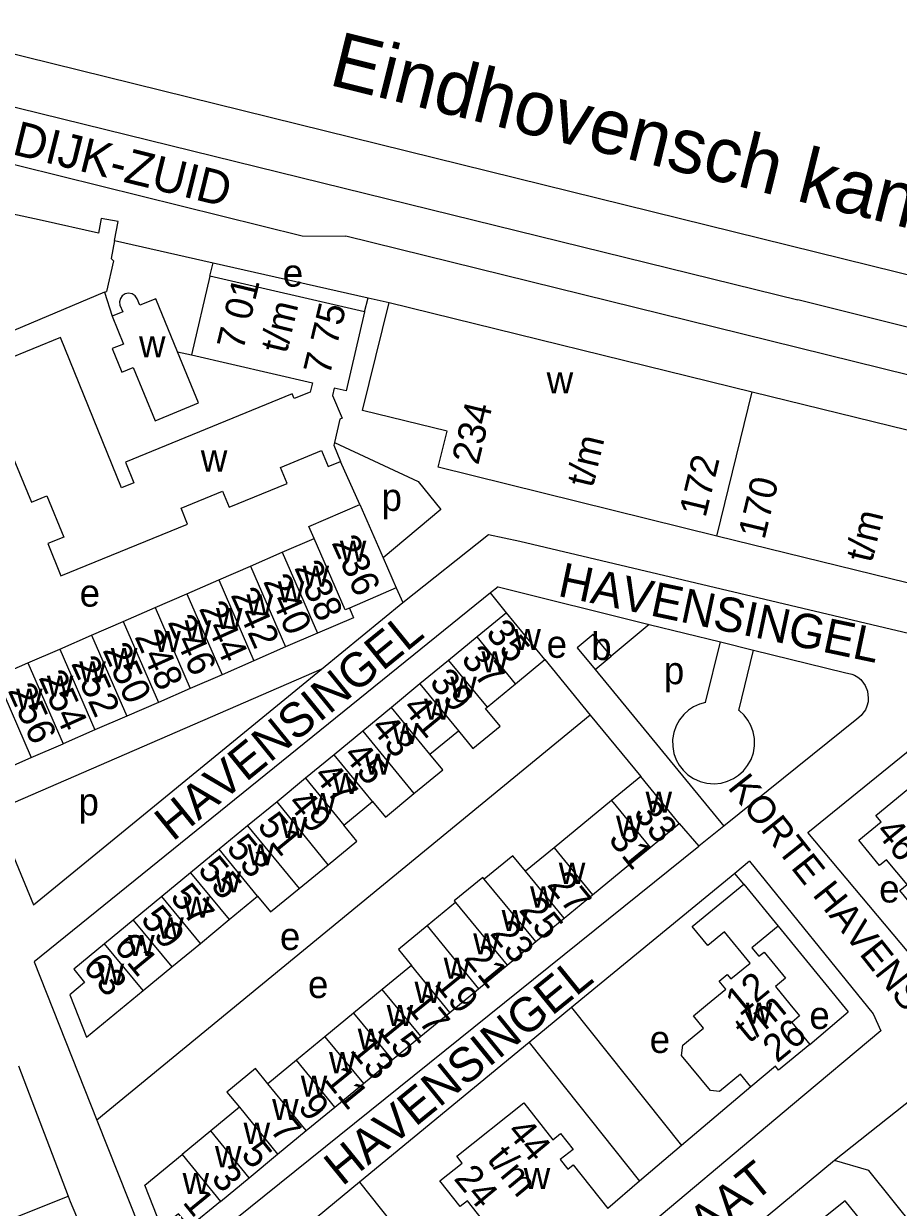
# Model space of a CAD drawing. Extents: x 161141 to 163125, y 381621 to 383200.
# Drawn here: x 161949.3 to 162076.7, y 382970.4 to 383142.8 of the extents above; entities that cross this region are included whole.
import ezdxf

# ---------------------------------------------------------------- set-up
doc = ezdxf.new("R2010")
doc.units = 0
for name, color, linetype in [('BLT_Basislijn', 7, 'Continuous'), ('BLT_Bebouwing', 7, 'Continuous'), ('BLT_Centroide', 7, 'Continuous'), ('BLT_Huisnummer', 7, 'Continuous'), ('BLT_Huisnummer_ tussenligend', 7, 'Continuous'), ('BLT_Huisnummer_reeks', 7, 'Continuous'), ('BLT_Onderverdeling_panden', 7, 'Continuous'), ('BLT_Straatnaam', 7, 'Continuous'), ('BLT_Vlakafsluiter', 7, 'Continuous'), ('BLT_Waternaam_spoorwegen', 7, 'Continuous')]:
    doc.layers.add(name, color=color, linetype=linetype)

msp = doc.modelspace()

# ---------------------------------------------------------------- linework, layer by layer
at = {"layer": 'BLT_Basislijn'}
for p, q in [((161930.08, 383142.85), (162162.91, 383085.35)), ((161940.74, 383132.45), (162062.11, 383102.59)), ((162049.96, 383098.62), (161996.22, 383111.86)), ((161962.54, 383111.24), (161976.92, 383108)), ((161976.41, 383106.07), (161976.92, 383108)), ((161976.92, 383108), (161999.47, 383102.91)), ((161961.09, 383103.72), (161962.2, 383100.21)), ((161998.98, 383100.85), (161999.47, 383102.91)), ((161999.47, 383102.91), (162002.55, 383102.22)), ((161971.72, 383095.01), (161973.74, 383094.58)), ((161998.26, 383072.8), (161995.46, 383079.07)), ((162003.56, 383060.66), (162004.54, 383058.52)), ((161992.67, 383048.8), (162004.54, 383058.52)), ((162019.63, 383057.02), (162017.33, 383059.89)), ((162048.63, 383043.94), (162050.81, 383052.77)), ((162053.5, 383042.79), (162055.66, 383051.57)), ((162025.22, 383050.18), (162031.86, 383042.1)), ((161992.67, 383048.8), (161945.03, 383028.11)), ((162031.86, 383042.1), (161959.96, 382983.09)), ((162031.86, 383042.1), (162039.2, 383033.15)), ((162044.82, 383026.32), (162047.68, 383022.98)), ((162051.3, 383025.9), (162047.68, 383022.98)), ((162055.07, 383020.8), (162052.92, 383019.04)), ((162052.92, 383019.04), (162029.14, 382999.47)), ((162054.21, 383017.47), (162052.92, 383019.04)), ((162059.25, 383011.35), (162069.42, 382998.87)), ((162029.14, 382999.47), (162022.96, 382994.38)), ((162063.84, 382994.12), (162069.42, 382998.87)), ((162022.96, 382994.38), (161998.24, 382974.04)), ((162022.96, 382994.38), (162039.04, 382974.17)), ((161948.53, 382991.01), (161955.76, 382972.02)), ((162055.23, 382987.95), (162045.14, 382979.36)), ((162045.14, 382979.36), (162039.04, 382974.17)), ((161998.24, 382974.04), (161992.06, 382968.95)), ((162039.04, 382974.17), (162034.4, 382970.22)), ((161932.99, 382962.83), (161955.76, 382972.02))]:
    msp.add_line(p, q, dxfattribs=at)
for points in [[(161919.31, 383129.41), (161989.89, 383111.92), (161996.22, 383111.86)], [(162151.84, 383081.16), (162138.64, 383083.46), (162062.11, 383102.59)], [(162150.16, 383071.14), (162119.18, 383081.51), (162049.96, 383098.62)], [(161994.6, 383081.83), (162006.79, 383076.12), (162010.09, 383072.07), (162001.66, 383065.01)], [(162004.54, 383058.52), (162017.04, 383068.43), (162021.59, 383067.42)], [(162021.59, 383067.42), (162082.93, 383052.93)], [(162018.42, 383060.77), (162017.33, 383059.89)], [(162018.42, 383060.77), (162040.46, 383055.32)], [(162017.33, 383059.89), (161950.81, 383006.16), (161959.96, 382983.09)], [(162040.46, 383055.32), (162034.89, 383050.66)], [(162040.46, 383055.32), (162050.81, 383052.77)], [(162050.81, 383052.77), (162055.66, 383051.57)], [(162055.66, 383051.57), (162068.91, 383048.3), (162069.96, 383048.05), (162070.38, 383047.93), (162070.86, 383047.62), (162071.3, 383047.29), (162071.68, 383046.75), (162071.91, 383046.42), (162072.25, 383045.6)], [(161945.03, 383028.11), (161950.71, 383014.47), (161992.67, 383048.8)], [(162032.58, 383048.72), (162051.3, 383025.9)], [(162072.25, 383045.6), (162072.36, 383044.56), (162072.34, 383044.01), (162072.15, 383043.4), (162071.94, 383042.86), (162071.58, 383042.37), (162071.35, 383042.02), (162070.71, 383041.5), (162051.3, 383025.9)], [(162048.63, 383043.94), (162047.78, 383043.71), (162046.92, 383043.32), (162046.17, 383042.82), (162045.47, 383042.19), (162044.86, 383041.42), (162044.36, 383040.53), (162044.02, 383039.55), (162043.85, 383038.52), (162043.87, 383037.5), (162044.05, 383036.51), (162044.38, 383035.6), (162044.82, 383034.8)], [(162044.82, 383034.8), (162045.38, 383034.07), (162046.08, 383033.41), (162046.91, 383032.85), (162047.85, 383032.43), (162048.86, 383032.18), (162049.89, 383032.1), (162050.91, 383032.2), (162051.86, 383032.46), (162052.72, 383032.85), (162053.47, 383033.34), (162054.17, 383033.97), (162054.78, 383034.74), (162055.28, 383035.63), (162055.62, 383036.61), (162055.79, 383037.64), (162055.77, 383038.67), (162055.59, 383039.65), (162055.26, 383040.56), (162054.82, 383041.36)], [(162054.82, 383041.36), (162054.26, 383042.09), (162053.56, 383042.75), (162053.5, 383042.79)], [(162079.29, 383006.24), (162063.54, 383024.97), (162082.54, 383040.38)], [(161959.96, 382983.09), (161969.17, 382959.86), (162047.68, 383022.98)], [(162055.07, 383020.8), (162073.06, 382998.55), (162074.21, 382996.11), (162061.33, 382985.3), (162036.1, 382964.14), (162021.9, 382952.54)], [(162029.14, 382999.47), (162045.14, 382979.36)], [(162067.43, 382977.19), (162051.8, 382964.24)], [(162134.11, 382898.87), (162072.44, 382975.73), (162067.43, 382977.19)], [(161998.24, 382974.04), (162010.67, 382958.41), (162004.41, 382953.43)], [(161955.76, 382972.02), (161956.08, 382971.21), (161959.35, 382963.42), (161964.45, 382950.31), (161972.02, 382931.93), (161975.96, 382922.03)]]:
    msp.add_lwpolyline(points, dxfattribs=at)
at = {"layer": 'BLT_Bebouwing'}
for p, q in [((161951.99, 383114.15), (161922.23, 383120.74)), ((161961.09, 383103.72), (161961.35, 383103.82)), ((162002.55, 383102.22), (162055.46, 383089.21)), ((162055.46, 383089.21), (162103.01, 383077.48)), ((161986.98, 383065.82), (161991.6, 383067.83)), ((162090.75, 383058.21), (162050.29, 383068.19)), ((161982.34, 383063.8), (161986.98, 383065.82)), ((161977.71, 383061.79), (161982.34, 383063.8)), ((161973.08, 383059.77), (161977.71, 383061.79)), ((161968.45, 383057.76), (161973.08, 383059.77)), ((161963.81, 383055.75), (161968.45, 383057.76)), ((162019.63, 383057.02), (162015.37, 383053.51)), ((162025.22, 383050.18), (162019.63, 383057.02)), ((161959.18, 383053.73), (161963.81, 383055.75)), ((161954.55, 383051.72), (161959.18, 383053.73)), ((161992.1, 383054.03), (161987.47, 383052.02)), ((162015.37, 383053.51), (162011.2, 383050.07)), ((161949.92, 383049.7), (161954.55, 383051.72)), ((161987.47, 383052.02), (161982.84, 383050)), ((162029.96, 383051.9), (162032.58, 383048.72)), ((161982.84, 383050), (161978.2, 383047.98)), ((162011.2, 383050.07), (162007.04, 383046.64)), ((162020.95, 383046.67), (162025.22, 383050.18)), ((161945.28, 383047.69), (161949.92, 383049.7)), ((161978.2, 383047.98), (161973.57, 383045.97)), ((162007.04, 383046.64), (162002.87, 383043.2)), ((162016.81, 383043.25), (162020.95, 383046.67)), ((161973.57, 383045.97), (161968.94, 383043.95)), ((161968.94, 383043.95), (161964.31, 383041.94)), ((162002.87, 383043.2), (161998.71, 383039.77)), ((161964.31, 383041.94), (161959.67, 383039.93)), ((161959.67, 383039.93), (161955.04, 383037.91)), ((161998.71, 383039.77), (161994.54, 383036.33)), ((162008.48, 383036.39), (162012.64, 383039.82)), ((161950.41, 383035.9), (161955.04, 383037.91)), ((161994.54, 383036.33), (161990.37, 383032.91)), ((161990.37, 383032.91), (161986.21, 383029.48)), ((162039.2, 383033.15), (162034.96, 383029.65)), ((162044.82, 383026.32), (162039.2, 383033.15)), ((161986.21, 383029.48), (161981.93, 383025.96)), ((161995.97, 383026.07), (162000.14, 383029.52)), ((162034.96, 383029.65), (162030.75, 383026.19)), ((161981.93, 383025.96), (161977.78, 383022.54)), ((162030.75, 383026.19), (162026.6, 383022.76)), ((162040.59, 383022.82), (162044.82, 383026.32)), ((161977.78, 383022.54), (161973.6, 383019.1)), ((162026.6, 383022.76), (162022.44, 383019.34)), ((162036.38, 383019.36), (162040.59, 383022.82)), ((161973.6, 383019.1), (161969.43, 383015.66)), ((161989.43, 383016.82), (161993.65, 383020.27)), ((162032.16, 383015.89), (162036.38, 383019.36)), ((162046.72, 383011.3), (162054.21, 383017.47)), ((161969.43, 383015.66), (161965.25, 383012.22)), ((161979.24, 383012.29), (161983.38, 383015.7)), ((162028.07, 383012.53), (162032.16, 383015.89)), ((162012.21, 383014.8), (162008.08, 383011.39)), ((161965.25, 383012.22), (161961.07, 383008.78)), ((161975.05, 383008.83), (161979.24, 383012.29)), ((162023.91, 383009.09), (162028.07, 383012.53)), ((161970.88, 383005.4), (161975.05, 383008.83)), ((162019.74, 383005.66), (162023.91, 383009.09)), ((161966.73, 383001.98), (161970.88, 383005.4)), ((162005.81, 383005.63), (162001.55, 383002.12)), ((162015.56, 383002.22), (162019.74, 383005.66)), ((162001.55, 383002.12), (161997.36, 382998.67)), ((162011.37, 382998.76), (162015.56, 383002.22)), ((161997.36, 382998.67), (161993.2, 382995.24)), ((162007.15, 382995.29), (162011.37, 382998.76)), ((161993.2, 382995.24), (161989.05, 382991.82)), ((162003, 382991.86), (162007.15, 382995.29)), ((161989.05, 382991.82), (161984.88, 382988.38)), ((161998.82, 382988.43), (162003, 382991.86)), ((161994.65, 382984.99), (161998.82, 382988.43)), ((161980.72, 382984.96), (161976.55, 382981.52)), ((161990.48, 382981.56), (161994.65, 382984.99)), ((161976.55, 382981.52), (161972.39, 382978.09)), ((161986.3, 382978.12), (161990.48, 382981.56)), ((161982.14, 382974.68), (161986.3, 382978.12)), ((161977.96, 382971.24), (161982.14, 382974.68))]:
    msp.add_line(p, q, dxfattribs=at)
for points in [[(161962.54, 383111.24), (161963.07, 383114.02), (161960.61, 383114.47), (161960.2, 383112.3), (161951.99, 383114.15)], [(161962.54, 383111.24), (161962.04, 383108.61), (161962.38, 383108.28), (161961.35, 383103.82)], [(161976.41, 383106.07), (161973.74, 383094.58)], [(161998.98, 383100.85), (161976.41, 383106.07)], [(161961.09, 383103.72), (161933.66, 383092.17), (161935.31, 383087.91), (161934.75, 383087.68)], [(161971.72, 383095.01), (161968.54, 383102.77), (161966.2, 383101.84), (161965.85, 383102.76), (161965.56, 383103.19), (161965.12, 383103.48), (161964.59, 383103.59), (161964.06, 383103.47), (161963.66, 383103.19), (161963.39, 383102.79), (161963.28, 383102.33), (161963.33, 383101.85)], [(161963.33, 383101.85), (161963.75, 383100.84), (161962.2, 383100.21)], [(162050.29, 383068.19), (162009.71, 383078.21), (162011, 383083.45), (161998.67, 383086.49), (162002.55, 383102.22)], [(161962.2, 383100.21), (161963.84, 383096.16), (161962.21, 383095.5), (161963.6, 383092.08), (161965.23, 383092.74), (161968.44, 383084.97), (161974.77, 383087.58), (161971.72, 383095.01)], [(161998.98, 383100.85), (161996.3, 383089.35), (161994.56, 383089.74), (161994.31, 383088.69), (161995.69, 383085.34), (161995.37, 383085.21), (161994.6, 383081.83)], [(161973.74, 383094.58), (161991.37, 383090.5), (161991.03, 383089.16), (161988.7, 383088.23), (161988.43, 383088.89), (161964.15, 383078.93), (161965.36, 383075.96), (161963.55, 383075.22), (161954.67, 383097.12), (161942.54, 383092.16)], [(161946.96, 383081.57), (161950.43, 383073.11), (161952.67, 383074.03), (161955.13, 383068.03), (161952.81, 383067.08), (161954.73, 383062.38), (161973.18, 383069.94), (161972.23, 383072.24), (161978.27, 383074.72), (161979.23, 383072.38), (161987.67, 383075.84), (161986.71, 383078.18), (161992.71, 383080.63), (161993.66, 383078.3), (161995.46, 383079.07)], [(161994.6, 383081.83), (161994.5, 383081.41), (161995.46, 383079.07)], [(161991.6, 383067.83), (161990.84, 383069.58), (161998.26, 383072.8)], [(161998.26, 383072.8), (162001.66, 383065.01)], [(162001.66, 383065.01), (162003.56, 383060.66)], [(162003.56, 383060.66), (161996.75, 383057.68)], [(161996.75, 383057.68), (161997.35, 383056.29), (161992.1, 383054.03)], [(162034.89, 383050.66), (162032.29, 383053.82), (162029.96, 383051.9)], [(162032.58, 383048.72), (162034.89, 383050.66)], [(162012.64, 383039.82), (162014.76, 383037.24), (162018.71, 383040.49), (162016.58, 383043.07), (162016.81, 383043.25)], [(162006.17, 383030.65), (162010.37, 383034.1), (162008.48, 383036.39)], [(161943, 383032.68), (161950.41, 383035.9)], [(162000.14, 383029.52), (162002.02, 383027.23), (162006.17, 383030.65)], [(161993.65, 383020.27), (161997.86, 383023.71), (161995.97, 383026.07)], [(162022.44, 383019.34), (162020.56, 383021.6), (162016.41, 383018.17)], [(162016.41, 383018.17), (162016.18, 383018.45), (162012.02, 383015.03), (162012.21, 383014.8)], [(162054.21, 383017.47), (162059.25, 383011.35)], [(161983.38, 383015.7), (161985.26, 383013.41), (161989.43, 383016.82)], [(162008.08, 383011.39), (162003.9, 383007.95), (162005.81, 383005.63)], [(162055.23, 382987.95), (162053.74, 382989.76), (162050.7, 382987.26), (162049.36, 382987.39), (162045.17, 382992.48), (162045.32, 382994), (162048.35, 382996.5), (162046.88, 382998.29), (162048.95, 383000), (162051.59, 383002.17), (162050.63, 383003.34), (162051.82, 383004.32), (162052.36, 383003.66), (162055.17, 383005.97), (162051.42, 383010.52), (162049, 383008.53), (162046.72, 383011.3)], [(162059.25, 383011.35), (162055.41, 383008.19), (162056.42, 383006.96), (162057.18, 383007.57), (162060.32, 383003.76), (162058.86, 383002.56), (162060.95, 383000), (162062.36, 382998.26), (162061.21, 382997.31), (162063.84, 382994.12)], [(161961.07, 383008.78), (161956.59, 383005.09), (161958.16, 383003.15), (161956.03, 383001.35), (161958.46, 382995.16), (161966.73, 383001.98)], [(162063.84, 382994.12), (162059.29, 382990.37), (162058.84, 382990.92), (162055.23, 382987.95)], [(161984.88, 382988.38), (161983.08, 382990.58), (161978.91, 382987.13), (161980.72, 382984.96)], [(162021.4, 382959.88), (162015.87, 382966.83), (162016.87, 382967.63), (162013.95, 382971.31), (162012.91, 382970.48), (162009.92, 382974.24), (162013.19, 382976.83), (162012.41, 382977.82), (162022.16, 382985.58), (162026.42, 382980.23), (162027.52, 382981.11), (162029.35, 382978.82), (162027.47, 382977.32), (162028.57, 382975.93), (162029.35, 382976.56), (162034.4, 382970.22)], [(161977.96, 382971.24), (161973.46, 382967.52), (161971.87, 382969.44), (161969.36, 382967.41), (161966.93, 382973.59), (161972.39, 382978.09)], [(162085.29, 382954.77), (162077.24, 382964.82), (162075.4, 382963.38), (162069.02, 382971.32), (162062.5, 382966.11)]]:
    msp.add_lwpolyline(points, dxfattribs=at)
msp.add_lwpolyline([(162083.06, 383035.39), (162087.39, 383030.15), (162088.46, 383031.04), (162090.39, 383028.7), (162088.46, 383027.11), (162089.59, 383025.73), (162090.41, 383026.41), (162095.49, 383020.26), (162082.65, 383009.65), (162076.96, 383016.54), (162078.01, 383017.4), (162075.01, 383021.02), (162074.02, 383020.2), (162070.99, 383023.88), (162074.24, 383026.56), (162073.48, 383027.48)], close=True, dxfattribs=at)
at = {"layer": 'BLT_Onderverdeling_panden'}
for p, q in [((162050.29, 383068.19), (162055.46, 383089.21)), ((161986.98, 383065.82), (161992.1, 383054.03)), ((161982.34, 383063.8), (161987.47, 383052.02)), ((161977.71, 383061.79), (161982.84, 383050)), ((161973.08, 383059.77), (161978.2, 383047.98)), ((161968.45, 383057.76), (161973.57, 383045.97)), ((161963.81, 383055.75), (161968.94, 383043.95)), ((161959.18, 383053.73), (161964.31, 383041.94)), ((162020.95, 383046.67), (162015.37, 383053.51)), ((161954.55, 383051.72), (161959.67, 383039.93)), ((162011.2, 383050.07), (162016.81, 383043.25)), ((161949.92, 383049.7), (161955.04, 383037.91)), ((161945.28, 383047.69), (161950.41, 383035.9)), ((162007.04, 383046.64), (162012.64, 383039.82)), ((162008.48, 383036.39), (162002.87, 383043.2)), ((161998.71, 383039.77), (162006.17, 383030.65)), ((162000.14, 383029.52), (161994.54, 383036.33)), ((161990.37, 383032.91), (161995.97, 383026.07)), ((161993.65, 383020.27), (161986.21, 383029.48)), ((162034.96, 383029.65), (162040.59, 383022.82)), ((161981.93, 383025.96), (161989.43, 383016.82)), ((161983.38, 383015.7), (161977.78, 383022.54)), ((162026.6, 383022.76), (162032.16, 383015.89)), ((161973.6, 383019.1), (161979.24, 383012.29)), ((162028.07, 383012.53), (162022.44, 383019.34)), ((162023.91, 383009.09), (162016.41, 383018.17)), ((161975.05, 383008.83), (161969.43, 383015.66)), ((162012.21, 383014.8), (162019.74, 383005.66)), ((161965.25, 383012.22), (161970.88, 383005.4)), ((162008.08, 383011.39), (162015.56, 383002.22)), ((161966.73, 383001.98), (161961.07, 383008.78)), ((162011.37, 382998.76), (162005.81, 383005.63)), ((162007.15, 382995.29), (162001.55, 383002.12)), ((161997.36, 382998.67), (162003, 382991.86)), ((161993.2, 382995.24), (161998.82, 382988.43)), ((161994.65, 382984.99), (161989.05, 382991.82)), ((161990.48, 382981.56), (161984.88, 382988.38)), ((161980.72, 382984.96), (161986.3, 382978.12)), ((161982.14, 382974.68), (161976.55, 382981.52)), ((161972.39, 382978.09), (161977.96, 382971.24))]:
    msp.add_line(p, q, dxfattribs=at)
msp.add_lwpolyline([(161996.75, 383057.68), (161996.14, 383057.42), (161991.6, 383067.83)], dxfattribs=at)
at = {"layer": 'BLT_Vlakafsluiter'}
msp.add_line((162078.89, 382986.26), (162067.43, 382977.19), dxfattribs=at)

# ---------------------------------------------------------------- texts
at = {"layer": 'BLT_Centroide'}
for s, p in [('e', (161987.05, 383104.53)), ('w', (161966.1, 383094.24)), ('w', (162025.5, 383088.96)), ('w', (161975.11, 383077.59)), ('p', (162001.44, 383071.85)), ('w', (161995.36, 383064.45)), ('w', (161989.93, 383060.8)), ('e', (161957.45, 383057.9)), ('w', (161986.32, 383058.51)), ('w', (161981.76, 383056.62)), ('w', (161977.32, 383054.62)), ('w', (161972.76, 383052.84)), ('w', (161968.32, 383051.28)), ('w', (162020.79, 383051.58)), ('e', (162025.5, 383050.44)), ('b', (162031.99, 383050.12)), ('w', (161962, 383048.78)), ('w', (161957.4, 383046.86)), ('w', (162016, 383048.31)), ('p', (162042.57, 383046.6)), ('w', (161952.67, 383044.78)), ('w', (162011.45, 383044.63)), ('w', (161948.19, 383042.9)), ('w', (162007.64, 383041.41)), ('w', (162002.97, 383037.89)), ('w', (161998.95, 383033.41)), ('w', (161994.28, 383030.61)), ('w', (162039.91, 383027.88)), ('p', (161957.28, 383027.47)), ('w', (161990.94, 383027.66)), ('w', (162035.61, 383024.38)), ('w', (161986.72, 383024.19)), ('w', (161981.9, 383020.19)), ('w', (162027.27, 383017.5)), ('w', (161977.12, 383016.28)), ('w', (162023.09, 383014.05)), ('e', (162073.95, 383014.79)), ('w', (161972.56, 383012.58)), ('w', (162018.94, 383010.62)), ('w', (161968.76, 383009.54)), ('e', (161986.63, 383007.87)), ('w', (162014.8, 383007.22)), ('w', (161964.52, 383006.98)), ('w', (162010.5, 383003.67)), ('w', (161960.07, 383002.81)), ('e', (161990.72, 383000.87)), ('w', (162006.25, 383000.17)), ('w', (162002.19, 382996.8)), ('w', (162054.52, 382997.14)), ('e', (162063.78, 382996.36)), ('w', (161997.97, 382993.34)), ('e', (162040.51, 382992.86)), ('w', (161993.8, 382989.92)), ('w', (161989.67, 382986.5)), ('w', (161985.5, 382983.09)), ('w', (161981.34, 382979.62)), ('w', (161977.17, 382976.22)), ('w', (162022.16, 382973.03)), ('w', (161972.45, 382972.3))]:
    msp.add_text(s, height=4, dxfattribs=at).set_placement(p)
at = {"layer": 'BLT_Huisnummer'}
for s, rotation, p in [('236', 294.2061, (161994.11, 383067.24)), ('240', 294.2061, (161984.13, 383061.59)), ('244', 294.2061, (161974.78, 383057.64)), ('35', 309.5105, (162016.5, 383053.98)), ('248', 294.2061, (161965.4, 383053.53)), ('252', 294.2061, (161956.15, 383049.64)), ('39', 309.5105, (162008.29, 383046.82)), ('256', 294.2061, (161946.93, 383045.7)), ('43', 309.5105, (161999.74, 383040.2)), ('47', 309.5058, (161991.4, 383033.19)), ('33', 309.2047, (162037.99, 383027.73)), ('51', 309.5097, (161983.2, 383025.91)), ('31', 309.2088, (162034.37, 383023.94)), ('55', 309.5097, (161974.52, 383019.51)), ('27', 309.2047, (162025.43, 383017.33)), ('25', 309.2047, (162021.33, 383013.65)), ('59', 309.5097, (161966.2, 383012.29)), ('21', 309.2056, (162013.33, 383006.62)), ('63', 309.5097, (161957.77, 383005.39)), ('17', 309.2065, (162004.82, 382999.68)), ('13', 309.2025, (161996.72, 382993.24)), ('9', 309.2034, (161989.13, 382984.93)), ('5', 309.2043, (161980.83, 382978.03)), ('1', 309.2052, (161972.34, 382971.07))]:
    msp.add_text(s, height=4, rotation=rotation, dxfattribs=at).set_placement(p)
at = {"layer": 'BLT_Huisnummer_ tussenligend'}
for s, rotation, p in [('238', 294.2061, (161988.67, 383063.58)), ('242', 294.2061, (161979.4, 383059.62)), ('246', 294.2061, (161970.22, 383055.66)), ('250', 294.2061, (161960.74, 383051.57)), ('37', 309.5105, (162012.9, 383050.19)), ('254', 294.2061, (161951.41, 383047.58)), ('41', 309.5105, (162004.36, 383043.09)), ('45', 309.5105, (161995.73, 383036.19)), ('49', 309.5058, (161987.6, 383029.18)), ('53', 309.5097, (161978.69, 383022.67)), ('57', 309.5097, (161970.5, 383015.51)), ('23', 309.2056, (162017.14, 383010.24)), ('61', 309.5097, (161962.27, 383008.35)), ('19', 309.2065, (162009.02, 383002.89)), ('15', 309.2025, (162000.67, 382996.22)), ('11', 309.2034, (161992.95, 382988.97)), ('7', 309.2043, (161985.04, 382981.63)), ('3', 309.2052, (161976.49, 382974.58))]:
    msp.add_text(s, height=4, rotation=rotation, dxfattribs=at).set_placement(p)
at = {"layer": 'BLT_Huisnummer_reeks'}
for s, rotation, p in [('7 01', 76.4442, (161981.27, 383095.11)), ('t/m', 76.4442, (161987.61, 383094.67)), ('7 75', 76.4442, (161993.88, 383091.45)), ('234', 76.4442, (162015.52, 383078.43)), ('t/m', 76.4442, (162032.21, 383075.12)), ('172', 76.4442, (162048.64, 383070.76)), ('170', 76.4442, (162057.23, 383067.55)), ('t/m', 76.4442, (162072.88, 383064.19)), ('46', 309.5254, (162073.29, 383025.06)), ('12', 39.4797, (162053.65, 382998.11)), ('t/m', 39.4747, (162054.98, 382994.16)), ('26', 39.4711, (162059.07, 382991.32)), ('44', 309.5254, (162019.56, 382981.32)), ('t/m', 309.5254, (162016.68, 382977.31)), ('24', 309.5254, (162011.85, 382974.52))]:
    msp.add_text(s, height=4, rotation=rotation, dxfattribs=at).set_placement(p)
at = {"layer": 'BLT_Straatnaam'}
for s, height, rotation, p in [('KANAALDIJK-ZUID', 5, 346.087, (161921.84, 383130.2)), ('HAVENSINGEL', 5, 348.1019, (162026.96, 383059.49)), ('HAVENSINGEL', 5, 39.114, (161971.02, 383023.59)), ('KORTE HAVENSTRAAT', 4, 308.414, (162051.75, 383031.51)), ('HAVENSINGEL', 5, 39.114, (161995.71, 382973.35)), ('TONGELRESESTRAAT', 5, 39.114, (162002.98, 382928.13))]:
    msp.add_text(s, height=height, rotation=rotation, dxfattribs=at).set_placement(p)
at = {"layer": 'BLT_Waternaam_spoorwegen'}
msp.add_text('Eindhovensch kanaal', height=8, rotation=346.0777, dxfattribs=at).set_placement((161993.57, 383133.98))

doc.saveas('drawing.dxf')
